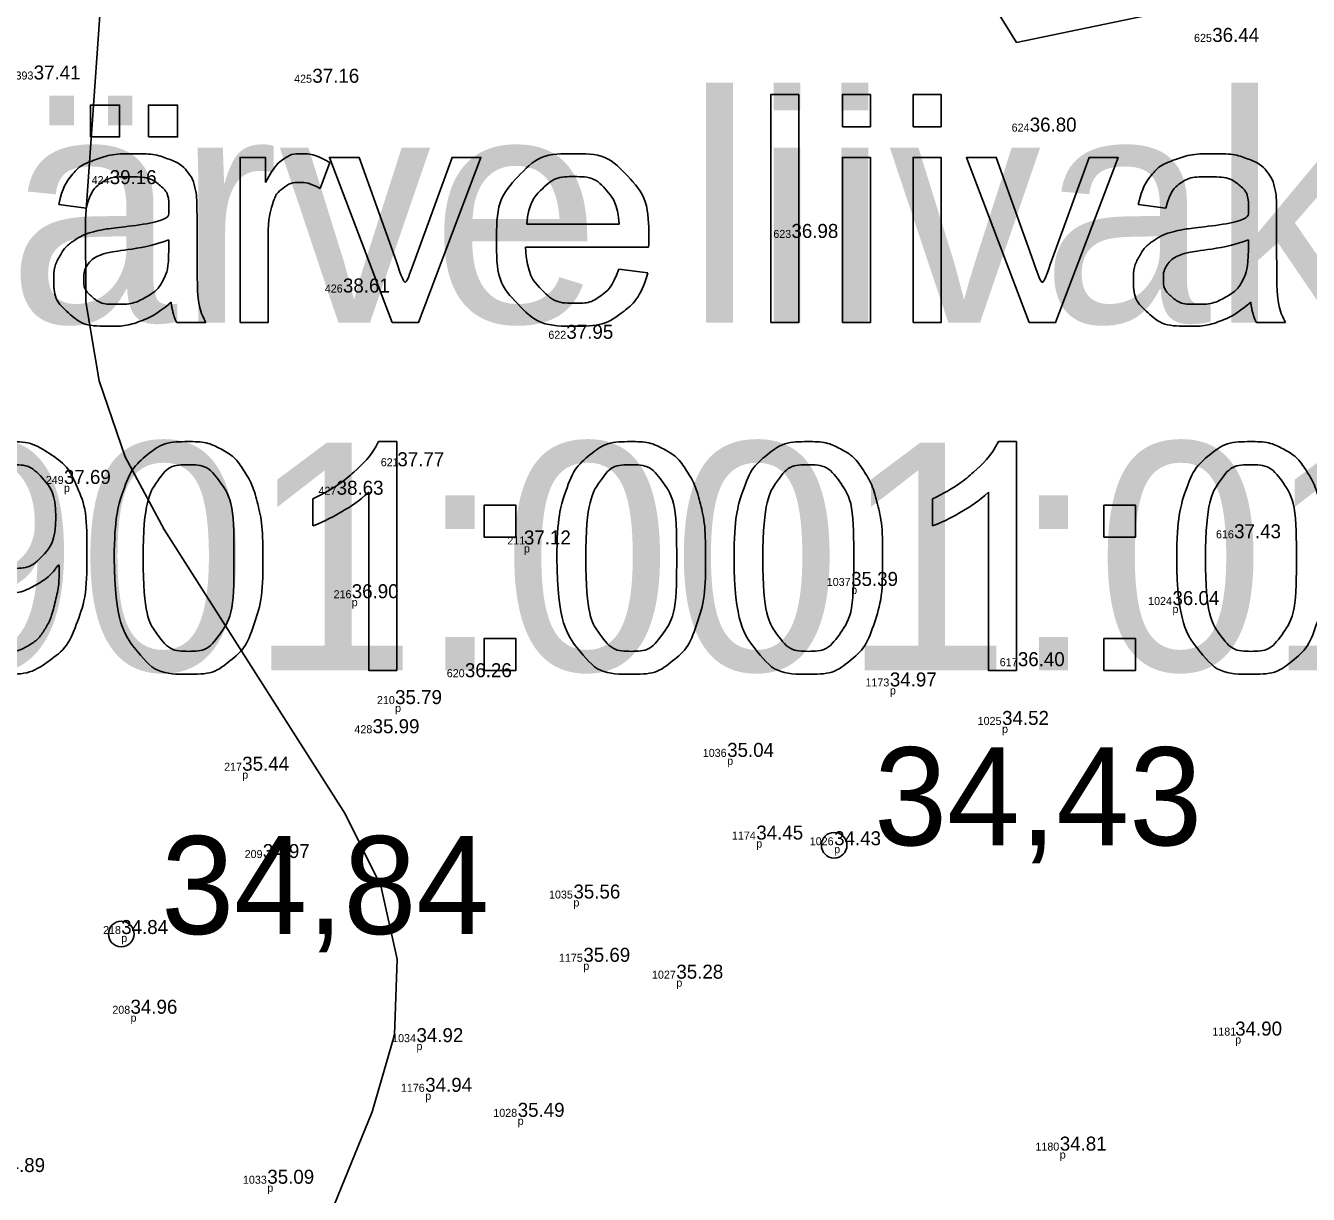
# Model space of a CAD drawing. Extents: x 700746 to 706058, y 6570320 to 6580460.
# Drawn here: x 702898.47 to 702930.53, y 6577214.62 to 6577243.85 of the extents above; entities that cross this region are included whole.
import ezdxf

# ---------------------------------------------------------------- set-up
doc = ezdxf.new("R2010")
doc.units = 0
for name, color, linetype in [('Kaevandatud ala', 7, 'Continuous'), ('kataster', 7, 'Continuous'), ('Kataster tekst', 7, 'Continuous'), ('KORGUS-EH2000', 7, 'Continuous'), ('Lamami horisontaal_EH2000', 7, 'Continuous'), ('MOOTKOOD', 7, 'Continuous'), ('MOOTKORG-EH2000', 7, 'Continuous'), ('MOOTNR', 7, 'Continuous')]:
    doc.layers.add(name, color=color, linetype=linetype)

msp = doc.modelspace()

# ---------------------------------------------------------------- linework, layer by layer
at = {"layer": 'Kaevandatud ala'}
msp.add_lwpolyline([(702883.006, 6577287.683), (702888.247, 6577285.595), (702892.428, 6577282.254), (702897.16, 6577280.37), (702901.941, 6577277.664), (702901.603, 6577275.308), (702911.185, 6577268.859), (702910.984, 6577262.539), (702910.646, 6577251.884), (702919.266, 6577249.854), (702923.239, 6577243.427), (702932.999, 6577245.456), (702942.381, 6577239.981), (702951.761, 6577239.728), (702966.129, 6577242.349), (702973.059, 6577233.977), (702979.82, 6577236.43), (702989.2, 6577237.36), (702992.919, 6577234.147), (702996.289, 6577226.894), (703003.652, 6577221.631), (703013.709, 6577214.443)], dxfattribs=at)
at = {"layer": 'kataster'}
for points in [[(702917.095, 6577236.421), (702917.095, 6577242.121), (702917.794, 6577242.121), (702917.794, 6577236.421), (702917.095, 6577236.421)], [(702918.885, 6577241.318), (702918.885, 6577242.121), (702919.584, 6577242.121), (702919.584, 6577241.318), (702918.885, 6577241.318)], [(702920.653, 6577241.318), (702920.653, 6577242.121), (702921.352, 6577242.121), (702921.352, 6577241.318), (702920.653, 6577241.318)], [(702900.086, 6577241.066), (702900.086, 6577241.861), (702900.816, 6577241.861), (702900.816, 6577241.066), (702900.086, 6577241.066)], [(702901.537, 6577241.066), (702901.537, 6577241.861), (702902.267, 6577241.861), (702902.267, 6577241.066), (702901.537, 6577241.066)], [(702903.831, 6577236.421), (702903.831, 6577240.553), (702904.461, 6577240.553), (702904.461, 6577239.927)], [(702906.073, 6577240.421), (702905.828, 6577239.773)], [(702907.628, 6577236.421), (702906.064, 6577240.553), (702906.803, 6577240.553), (702907.687, 6577238.079)], [(702908.212, 6577238.032), (702909.129, 6577240.553), (702909.848, 6577240.553), (702908.286, 6577236.421), (702907.628, 6577236.421)], [(702918.885, 6577236.421), (702918.885, 6577240.553), (702919.584, 6577240.553), (702919.584, 6577236.421), (702918.885, 6577236.421)], [(702920.653, 6577236.421), (702920.653, 6577240.553), (702921.352, 6577240.553), (702921.352, 6577236.421), (702920.653, 6577236.421)], [(702923.555, 6577236.421), (702921.991, 6577240.553), (702922.73, 6577240.553), (702923.614, 6577238.079)], [(702924.139, 6577238.032), (702925.056, 6577240.553), (702925.775, 6577240.553), (702924.213, 6577236.421), (702923.555, 6577236.421)], [(702899.982, 6577239.28), (702899.295, 6577239.371)], [(702902.753, 6577239.085), (702902.753, 6577238.152)], [(702926.97, 6577239.28), (702926.283, 6577239.371)], [(702929.741, 6577239.085), (702929.741, 6577238.152)], [(702910.999, 6577238.88), (702913.306, 6577238.88)], [(702902.046, 6577238.237), (702902.05, 6577238.494)], [(702904.53, 6577238.585), (702904.53, 6577236.421), (702903.831, 6577236.421)], [(702929.034, 6577238.237), (702929.038, 6577238.494)], [(702914.041, 6577238.307), (702910.96, 6577238.307)], [(702913.298, 6577237.755), (702914.021, 6577237.664)], [(702902.975, 6577236.421), (702902.245, 6577236.421)], [(702929.963, 6577236.421), (702929.233, 6577236.421)], [(702907.293, 6577233.444), (702907.744, 6577233.444), (702907.744, 6577227.722)], [(702922.785, 6577233.444), (702923.236, 6577233.444), (702923.236, 6577227.722)], [(702905.645, 6577231.337), (702905.645, 6577232.014)], [(702907.744, 6577227.722), (702907.044, 6577227.722), (702907.044, 6577232.181)], [(702921.138, 6577231.337), (702921.138, 6577232.014)], [(702923.236, 6577227.722), (702922.537, 6577227.722), (702922.537, 6577232.181)], [(702909.929, 6577231.059), (702909.929, 6577231.854), (702910.724, 6577231.854), (702910.724, 6577231.059), (702909.929, 6577231.059)], [(702925.421, 6577231.059), (702925.421, 6577231.854), (702926.216, 6577231.854), (702926.216, 6577231.059), (702925.421, 6577231.059)], [(702909.929, 6577227.722), (702909.929, 6577228.518), (702910.724, 6577228.518), (702910.724, 6577227.722), (702909.929, 6577227.722)], [(702925.421, 6577227.722), (702925.421, 6577228.518), (702926.216, 6577228.518), (702926.216, 6577227.722), (702925.421, 6577227.722)]]:
    msp.add_lwpolyline(points, dxfattribs=at)
for points, degree in [([(702899.295, 6577239.371), (702899.388, 6577239.811), (702899.602, 6577240.082), (702899.816, 6577240.352), (702900.22, 6577240.498), (702900.624, 6577240.644), (702901.156, 6577240.644), (702901.685, 6577240.644), (702902.015, 6577240.52), (702902.345, 6577240.395), (702902.501, 6577240.207), (702902.656, 6577240.018), (702902.718, 6577239.73), (702902.753, 6577239.551), (702902.753, 6577239.085)], 3), ([(702904.461, 6577239.927), (702904.702, 6577240.365), (702904.905, 6577240.505), (702905.109, 6577240.644), (702905.354, 6577240.644), (702905.708, 6577240.644), (702906.073, 6577240.421)], 3), ([(702914.021, 6577237.664), (702913.85, 6577237.03), (702913.388, 6577236.68), (702912.925, 6577236.33), (702912.206, 6577236.33), (702911.3, 6577236.33), (702910.77, 6577236.888), (702910.239, 6577237.446), (702910.239, 6577238.452), (702910.239, 6577239.494), (702910.775, 6577240.069), (702911.312, 6577240.644), (702912.167, 6577240.644), (702912.995, 6577240.644), (702913.52, 6577240.08), (702914.045, 6577239.516), (702914.045, 6577238.494), (702914.045, 6577238.431), (702914.041, 6577238.307)], 3), ([(702926.283, 6577239.371), (702926.377, 6577239.811), (702926.59, 6577240.082), (702926.804, 6577240.352), (702927.208, 6577240.498), (702927.612, 6577240.644), (702928.144, 6577240.644), (702928.673, 6577240.644), (702929.003, 6577240.52), (702929.334, 6577240.395), (702929.489, 6577240.207), (702929.644, 6577240.018), (702929.707, 6577239.73), (702929.741, 6577239.551), (702929.741, 6577239.085)], 3), ([(702902.106, 6577236.93), (702901.716, 6577236.601), (702901.356, 6577236.466), (702900.996, 6577236.33), (702900.584, 6577236.33), (702899.904, 6577236.33), (702899.539, 6577236.662), (702899.174, 6577236.994), (702899.174, 6577237.511), (702899.174, 6577237.814), (702899.311, 6577238.064), (702899.449, 6577238.315), (702899.673, 6577238.466), (702899.896, 6577238.618), (702900.176, 6577238.695), (702900.382, 6577238.75), (702900.798, 6577238.8), (702901.645, 6577238.901), (702902.046, 6577239.041), (702902.05, 6577239.185), (702902.05, 6577239.224), (702902.05, 6577239.653), (702901.852, 6577239.829), (702901.584, 6577240.066), (702901.056, 6577240.066), (702900.564, 6577240.066), (702900.329, 6577239.893), (702900.094, 6577239.72), (702899.982, 6577239.28)], 3), ([(702913.306, 6577238.88), (702913.259, 6577239.403), (702913.042, 6577239.665), (702912.707, 6577240.071), (702912.174, 6577240.071), (702911.692, 6577240.071), (702911.363, 6577239.747), (702911.034, 6577239.423), (702910.999, 6577238.88)], 3), ([(702929.094, 6577236.93), (702928.704, 6577236.601), (702928.344, 6577236.466), (702927.985, 6577236.33), (702927.573, 6577236.33), (702926.892, 6577236.33), (702926.527, 6577236.662), (702926.162, 6577236.994), (702926.162, 6577237.511), (702926.162, 6577237.814), (702926.3, 6577238.064), (702926.438, 6577238.315), (702926.661, 6577238.466), (702926.884, 6577238.618), (702927.164, 6577238.695), (702927.37, 6577238.75), (702927.786, 6577238.8), (702928.634, 6577238.901), (702929.034, 6577239.041), (702929.038, 6577239.185), (702929.038, 6577239.224), (702929.038, 6577239.653), (702928.84, 6577239.829), (702928.572, 6577240.066), (702928.044, 6577240.066), (702927.552, 6577240.066), (702927.317, 6577239.893), (702927.082, 6577239.72), (702926.97, 6577239.28)], 3), ([(702905.828, 6577239.773), (702905.572, 6577239.923), (702905.317, 6577239.923), (702905.088, 6577239.923), (702904.906, 6577239.785), (702904.725, 6577239.647), (702904.647, 6577239.402), (702904.53, 6577239.028), (702904.53, 6577238.585)], 3), ([(702902.05, 6577238.494), (702901.668, 6577238.338), (702900.905, 6577238.229), (702900.473, 6577238.167), (702900.294, 6577238.09), (702900.115, 6577238.012), (702900.018, 6577237.862), (702899.921, 6577237.713), (702899.921, 6577237.53), (702899.921, 6577237.25), (702900.132, 6577237.064), (702900.344, 6577236.878), (702900.752, 6577236.878), (702901.156, 6577236.878), (702901.471, 6577237.054), (702901.785, 6577237.231), (702901.933, 6577237.538), (702902.046, 6577237.775), (702902.046, 6577238.237)], 3), ([(702929.038, 6577238.494), (702928.656, 6577238.338), (702927.894, 6577238.229), (702927.462, 6577238.167), (702927.282, 6577238.09), (702927.103, 6577238.012), (702927.006, 6577237.862), (702926.909, 6577237.713), (702926.909, 6577237.53), (702926.909, 6577237.25), (702927.121, 6577237.064), (702927.332, 6577236.878), (702927.74, 6577236.878), (702928.144, 6577236.878), (702928.459, 6577237.054), (702928.774, 6577237.231), (702928.921, 6577237.538), (702929.034, 6577237.775), (702929.034, 6577238.237)], 3), ([(702902.753, 6577238.152), (702902.753, 6577237.177), (702902.798, 6577236.918), (702902.843, 6577236.659), (702902.975, 6577236.421)], 3), ([(702910.96, 6577238.307), (702910.999, 6577237.627), (702911.345, 6577237.265), (702911.692, 6577236.904), (702912.209, 6577236.904), (702912.594, 6577236.904), (702912.867, 6577237.107), (702913.139, 6577237.31), (702913.298, 6577237.755)], 3), ([(702929.741, 6577238.152), (702929.741, 6577237.177), (702929.786, 6577236.918), (702929.831, 6577236.659), (702929.963, 6577236.421)], 3), ([(702907.687, 6577238.079), (702907.831, 6577237.678), (702907.952, 6577237.246), (702908.045, 6577237.573), (702908.212, 6577238.032)], 3), ([(702923.614, 6577238.079), (702923.758, 6577237.678), (702923.879, 6577237.246), (702923.972, 6577237.573), (702924.139, 6577238.032)], 3), ([(702902.245, 6577236.421), (702902.137, 6577236.639), (702902.106, 6577236.93)], 2), ([(702929.233, 6577236.421), (702929.125, 6577236.639), (702929.094, 6577236.93)], 2), ([(702897.034, 6577229.104), (702897.12, 6577228.629), (702897.361, 6577228.415), (702897.601, 6577228.2), (702897.978, 6577228.2), (702898.3, 6577228.2), (702898.544, 6577228.348), (702898.788, 6577228.496), (702898.942, 6577228.743), (702899.096, 6577228.99), (702899.201, 6577229.411), (702899.306, 6577229.831), (702899.306, 6577230.266), (702899.306, 6577230.313), (702899.302, 6577230.406), (702899.092, 6577230.072), (702898.729, 6577229.864), (702898.366, 6577229.656), (702897.943, 6577229.656), (702897.236, 6577229.656), (702896.746, 6577230.169), (702896.257, 6577230.682), (702896.257, 6577231.521), (702896.257, 6577232.387), (702896.768, 6577232.916), (702897.278, 6577233.444), (702898.048, 6577233.444), (702898.603, 6577233.444), (702899.063, 6577233.145), (702899.524, 6577232.846), (702899.763, 6577232.292), (702900.002, 6577231.738), (702900.002, 6577230.689), (702900.002, 6577229.597), (702899.765, 6577228.95), (702899.528, 6577228.303), (702899.059, 6577227.965), (702898.591, 6577227.627), (702897.962, 6577227.627), (702897.293, 6577227.627), (702896.87, 6577227.998), (702896.446, 6577228.37), (702896.361, 6577229.043)], 3), ([(702900.684, 6577230.534), (702900.684, 6577231.544), (702900.892, 6577232.161), (702901.1, 6577232.778), (702901.509, 6577233.111), (702901.919, 6577233.444), (702902.541, 6577233.444), (702903, 6577233.444), (702903.346, 6577233.26), (702903.693, 6577233.075), (702903.918, 6577232.727), (702904.142, 6577232.379), (702904.27, 6577231.88), (702904.398, 6577231.381), (702904.398, 6577230.534), (702904.398, 6577229.531), (702904.192, 6577228.914), (702903.986, 6577228.297), (702903.577, 6577227.962), (702903.167, 6577227.627), (702902.541, 6577227.627), (702901.717, 6577227.627), (702901.247, 6577228.215), (702900.684, 6577228.929), (702900.684, 6577230.534)], 3), ([(702905.645, 6577232.014), (702906.232, 6577232.29), (702906.671, 6577232.682), (702907.11, 6577233.075), (702907.293, 6577233.444)], 3), ([(702911.749, 6577230.534), (702911.749, 6577231.544), (702911.957, 6577232.161), (702912.165, 6577232.778), (702912.575, 6577233.111), (702912.985, 6577233.444), (702913.607, 6577233.444), (702914.065, 6577233.444), (702914.412, 6577233.26), (702914.759, 6577233.075), (702914.983, 6577232.727), (702915.207, 6577232.379), (702915.336, 6577231.88), (702915.464, 6577231.381), (702915.464, 6577230.534), (702915.464, 6577229.531), (702915.258, 6577228.914), (702915.052, 6577228.297), (702914.642, 6577227.962), (702914.232, 6577227.627), (702913.607, 6577227.627), (702912.783, 6577227.627), (702912.313, 6577228.215), (702911.749, 6577228.929), (702911.749, 6577230.534)], 3), ([(702916.176, 6577230.534), (702916.176, 6577231.544), (702916.384, 6577232.161), (702916.592, 6577232.778), (702917.002, 6577233.111), (702917.412, 6577233.444), (702918.034, 6577233.444), (702918.492, 6577233.444), (702918.839, 6577233.26), (702919.186, 6577233.075), (702919.41, 6577232.727), (702919.634, 6577232.379), (702919.763, 6577231.88), (702919.891, 6577231.381), (702919.891, 6577230.534), (702919.891, 6577229.531), (702919.685, 6577228.914), (702919.479, 6577228.297), (702919.069, 6577227.962), (702918.659, 6577227.627), (702918.034, 6577227.627), (702917.21, 6577227.627), (702916.74, 6577228.215), (702916.176, 6577228.929), (702916.176, 6577230.534)], 3), ([(702921.138, 6577232.014), (702921.725, 6577232.29), (702922.164, 6577232.682), (702922.603, 6577233.075), (702922.785, 6577233.444)], 3), ([(702927.242, 6577230.534), (702927.242, 6577231.544), (702927.45, 6577232.161), (702927.658, 6577232.778), (702928.067, 6577233.111), (702928.477, 6577233.444), (702929.099, 6577233.444), (702929.558, 6577233.444), (702929.904, 6577233.26), (702930.251, 6577233.075), (702930.476, 6577232.727), (702930.7, 6577232.379), (702930.828, 6577231.88), (702930.956, 6577231.381), (702930.956, 6577230.534), (702930.956, 6577229.531), (702930.75, 6577228.914), (702930.544, 6577228.297), (702930.135, 6577227.962), (702929.725, 6577227.627), (702929.099, 6577227.627), (702928.275, 6577227.627), (702927.805, 6577228.215), (702927.242, 6577228.929), (702927.242, 6577230.534)], 3), ([(702899.224, 6577231.556), (702899.224, 6577232.159), (702898.905, 6577232.513), (702898.586, 6577232.866), (702898.134, 6577232.866), (702897.666, 6577232.866), (702897.322, 6577232.485), (702896.978, 6577232.104), (702896.978, 6577231.498), (702896.978, 6577230.953), (702897.305, 6577230.613), (702897.631, 6577230.273), (702898.115, 6577230.273), (702898.599, 6577230.273), (702898.912, 6577230.613), (702899.224, 6577230.953), (702899.224, 6577231.556)], 3), ([(702901.405, 6577230.533), (702901.405, 6577229.128), (702901.733, 6577228.664), (702902.06, 6577228.2), (702902.541, 6577228.2), (702903.022, 6577228.2), (702903.349, 6577228.666), (702903.677, 6577229.131), (702903.677, 6577230.533), (702903.677, 6577231.941), (702903.35, 6577232.404), (702903.023, 6577232.866), (702902.533, 6577232.866), (702902.052, 6577232.866), (702901.764, 6577232.458), (702901.405, 6577231.937), (702901.405, 6577230.533)], 3), ([(702912.47, 6577230.533), (702912.47, 6577229.128), (702912.798, 6577228.664), (702913.126, 6577228.2), (702913.607, 6577228.2), (702914.087, 6577228.2), (702914.415, 6577228.666), (702914.743, 6577229.131), (702914.743, 6577230.533), (702914.743, 6577231.941), (702914.416, 6577232.404), (702914.088, 6577232.866), (702913.599, 6577232.866), (702913.118, 6577232.866), (702912.83, 6577232.458), (702912.47, 6577231.937), (702912.47, 6577230.533)], 3), ([(702916.897, 6577230.533), (702916.897, 6577229.128), (702917.225, 6577228.664), (702917.553, 6577228.2), (702918.034, 6577228.2), (702918.514, 6577228.2), (702918.842, 6577228.666), (702919.17, 6577229.131), (702919.17, 6577230.533), (702919.17, 6577231.941), (702918.843, 6577232.404), (702918.515, 6577232.866), (702918.026, 6577232.866), (702917.545, 6577232.866), (702917.257, 6577232.458), (702916.897, 6577231.937), (702916.897, 6577230.533)], 3), ([(702927.963, 6577230.533), (702927.963, 6577229.128), (702928.291, 6577228.664), (702928.618, 6577228.2), (702929.099, 6577228.2), (702929.58, 6577228.2), (702929.907, 6577228.666), (702930.235, 6577229.131), (702930.235, 6577230.533), (702930.235, 6577231.941), (702929.908, 6577232.404), (702929.581, 6577232.866), (702929.091, 6577232.866), (702928.61, 6577232.866), (702928.322, 6577232.458), (702927.963, 6577231.937), (702927.963, 6577230.533)], 3), ([(702907.044, 6577232.181), (702906.792, 6577231.94), (702906.382, 6577231.699), (702905.972, 6577231.458), (702905.645, 6577231.337)], 3), ([(702922.537, 6577232.181), (702922.284, 6577231.94), (702921.874, 6577231.699), (702921.464, 6577231.458), (702921.138, 6577231.337)], 3)]:
    msp.add_open_spline(points, degree=degree, dxfattribs=at)
at = {"layer": 'KORGUS-EH2000'}
for centre in [(702918.679, 6577223.351), (702900.858, 6577221.131)]:
    msp.add_circle(centre, 0.32, dxfattribs=at)
at = {"layer": 'Lamami horisontaal_EH2000'}
msp.add_lwpolyline([(702902.362, 6577273.159), (702899.964, 6577239.004), (702899.976, 6577236.943), (702900.308, 6577234.963), (702900.96, 6577233.064), (702901.932, 6577231.247), (702906.46, 6577224.139), (702907.351, 6577222.34), (702907.76, 6577220.498), (702907.687, 6577218.613), (702907.132, 6577216.684), (702901.836, 6577203.709), (702901.564, 6577202.882), (702901.417, 6577202.043), (702901.397, 6577201.192), (702901.503, 6577200.328), (702902.177, 6577196.848), (702902.332, 6577195.976), (702902.46, 6577195.101), (702902.562, 6577194.222), (702902.636, 6577193.339), (702902.748, 6577191.73)], dxfattribs=at)

# ---------------------------------------------------------------- texts
at = {"layer": 'Kataster tekst'}
for s, p in [('Pannjärve liivakarjäär', (702878.524, 6577236.421)), ('22901:001:0160', (702887.072, 6577227.722))]:
    msp.add_text(s, height=5.7, dxfattribs=at).set_placement(p)
at = {"layer": 'KORGUS-EH2000'}
for s, p in [('34,43', (702919.679, 6577223.351)), ('34,84', (702901.858, 6577221.131))]:
    msp.add_text(s, height=2.45, dxfattribs=at).set_placement(p)
at = {"layer": 'MOOTKOOD'}
for p in [(702899.426, 6577232.186), (702910.925, 6577230.672), (702919.104, 6577229.635), (702906.62, 6577229.328), (702927.136, 6577229.158), (702920.072, 6577227.122), (702907.704, 6577226.681), (702922.877, 6577226.16), (702916.005, 6577225.361), (702903.883, 6577225.015), (702916.733, 6577223.293), (702918.679, 6577223.151), (702904.398, 6577222.831), (702912.162, 6577221.818), (702900.858, 6577220.931), (702912.41, 6577220.236), (702914.735, 6577219.814), (702901.09, 6577218.937), (702928.704, 6577218.391), (702908.238, 6577218.227), (702908.458, 6577216.985), (702910.769, 6577216.359), (702924.319, 6577215.515), (702904.51, 6577214.686)]:
    msp.add_text('p', height=0.2, dxfattribs=at).set_placement(p)
at = {"layer": 'MOOTKORG-EH2000'}
for s, p in [('36.44', (702928.131, 6577243.44)), ('37.41', (702898.669, 6577242.5)), ('37.16', (702905.636, 6577242.419)), ('36.80', (702923.568, 6577241.197)), ('39.16', (702900.571, 6577239.884)), ('36.98', (702917.612, 6577238.538)), ('38.61', (702906.4, 6577237.173)), ('37.95', (702911.986, 6577236.015)), ('37.77', (702907.761, 6577232.829)), ('37.69', (702899.426, 6577232.386)), ('38.63', (702906.243, 6577232.116)), ('37.43', (702928.677, 6577231.027)), ('37.12', (702910.925, 6577230.872)), ('35.39', (702919.104, 6577229.835)), ('36.90', (702906.62, 6577229.528)), ('36.04', (702927.136, 6577229.358)), ('36.40', (702923.272, 6577227.829)), ('36.26', (702909.449, 6577227.553)), ('34.97', (702920.072, 6577227.322)), ('35.79', (702907.704, 6577226.881)), ('34.52', (702922.877, 6577226.36)), ('35.99', (702907.142, 6577226.153)), ('35.04', (702916.005, 6577225.561)), ('35.44', (702903.883, 6577225.215)), ('34.45', (702916.733, 6577223.493)), ('34.43', (702918.679, 6577223.351)), ('34.97', (702904.398, 6577223.031)), ('35.56', (702912.162, 6577222.018)), ('34.84', (702900.858, 6577221.131)), ('35.69', (702912.41, 6577220.436)), ('35.28', (702914.735, 6577220.014)), ('34.96', (702901.09, 6577219.137)), ('34.90', (702928.704, 6577218.591)), ('34.92', (702908.238, 6577218.427)), ('34.94', (702908.458, 6577217.185)), ('35.49', (702910.769, 6577216.559)), ('34.81', (702924.319, 6577215.715)), ('34.89', (702897.783, 6577215.178)), ('35.09', (702904.51, 6577214.886))]:
    msp.add_text(s, height=0.35, dxfattribs=at).set_placement(p)
at = {"layer": 'MOOTNR'}
for s, p in [('625', (702927.676, 6577243.44)), ('393', (702898.216, 6577242.5)), ('425', (702905.181, 6577242.419)), ('624', (702923.116, 6577241.197)), ('424', (702900.119, 6577239.884)), ('623', (702917.159, 6577238.538)), ('426', (702905.947, 6577237.173)), ('622', (702911.535, 6577236.015)), ('621', (702907.346, 6577232.829)), ('249', (702898.972, 6577232.386)), ('427', (702905.79, 6577232.116)), ('211', (702910.51, 6577230.872)), ('616', (702928.224, 6577231.027)), ('1037', (702918.495, 6577229.835)), ('216', (702906.167, 6577229.528)), ('1024', (702926.528, 6577229.358)), ('617', (702922.819, 6577227.829)), ('620', (702908.996, 6577227.553)), ('1173', (702919.463, 6577227.322)), ('210', (702907.251, 6577226.881)), ('1025', (702922.267, 6577226.36)), ('428', (702906.688, 6577226.153)), ('1036', (702915.396, 6577225.561)), ('217', (702903.43, 6577225.215)), ('1174', (702916.125, 6577223.493)), ('1026', (702918.07, 6577223.351)), ('209', (702903.944, 6577223.031)), ('1035', (702911.552, 6577222.018)), ('218', (702900.404, 6577221.131)), ('1175', (702911.8, 6577220.436)), ('1027', (702914.126, 6577220.014)), ('208', (702900.636, 6577219.137)), ('1034', (702907.63, 6577218.427)), ('1181', (702928.134, 6577218.591)), ('1176', (702907.849, 6577217.185)), ('1028', (702910.16, 6577216.559)), ('1180', (702923.711, 6577215.715)), ('1033', (702903.901, 6577214.886))]:
    msp.add_text(s, height=0.2, dxfattribs=at).set_placement(p)

doc.saveas('drawing.dxf')
